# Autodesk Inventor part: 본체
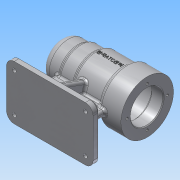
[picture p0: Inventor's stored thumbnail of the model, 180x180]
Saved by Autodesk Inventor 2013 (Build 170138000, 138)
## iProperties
Created: 2016-06
Part Number: 본체
Material: 알루미늄 6061
Document SubType Name: Modeling
Designer: Administrator
Density: 2.71 g/cm^3
Mass: 673.897 g
Surface Area: 647.231 cm^2
Volume: 248.671 cm^3
Author: Administrator
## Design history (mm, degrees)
sketch "스케치1"
  geometry: L1 (-56, 0)-(56, 0); L2 (56, 0)-(56, 34); L3 (56, 34)-(28, 34); L4 (28, 34)-(28, 30); L5 (28, 30)-(-11, 30); L6 (-11, 30)-(-11, 27); L7 (-11, 27)-(-31, 27); L8 (-31, 27)-(-31, 25); L9 (-31, 25)-(-56, 25); L10 (-56, 25)-(-56, 0); 1 further point
  constraints: 20 end point, 6 parallel, 2 vertical, 1 horizontal, 1 midpoint, 1 perpendicular
  dimensions: "d0" = 112 distance of L1.start L1.end; "d2" = 56 distance of point (0, 0) L1.start; "d3" = 68 diameter of L3 L1; "d5" = 60 diameter of L5 L1; "d6" = 54 diameter of L7 L1; "d7" = 50 diameter of L9 L1; "d8" = 25 distance of L8.end L9.end; "d9" = 45 distance between parallel lines of L6 L10; "d10" = 84 distance between parallel lines of L4 L10
revolve "회전1" sketch "스케치1" stored, may be unused: angle "d11" = 90 deg
node "작업 평면1"
sketch "스케치2"
  geometry: L1 (56, 35)-(-56, 35); L2 (-56, 35)-(-56, -35); L3 (-56, -35)-(56, -35); L4 (56, -35)-(56, 35); L5 (56, 35)-(-56, -35); L6 (-56, 35)-(56, -35); 1 further point
  constraints: 12 end point, 2 midpoint, 2 parallel, 1 horizontal, 1 perpendicular
  dimensions: "d13" = 112 distance of L1.start L1.end; "d15" = 70 distance of L1.end L2.end
extrude "돌출1" join sketch "스케치2" distance "d16" = 10; taper "d17" = 0 deg
hole "구멍1" diameter "d20" = 42; stored, may be unused: countersink angle "d24" = 90 deg, drill point angle "d26" = 0 deg; dims "d21" = 6, "d22" = 4, "d23" = 2, "d25" = 15, "d27" = 10, "d28" = 10
hole "구멍2" diameter "d31" = 42; stored, may be unused: countersink angle "d35" = 90 deg, drill point angle "d37" = 0 deg; dims "d29" = 10, "d30" = 10, "d32" = 6, "d33" = 48, "d34" = 54, "d36" = 66
hole "구멍3" diameter "d40" = 32; stored, may be unused: countersink angle "d44" = 90 deg, drill point angle "d46" = 0 deg; dims "d38" = 10, "d39" = 10, "d41" = 6, "d42" = 35, "d43" = 18, "d45" = 22
hole "구멍4" diameter "d49" = 21; stored, may be unused: countersink angle "d53" = 90 deg, drill point angle "d55" = 0 deg; dims "d47" = 10, "d48" = 10, "d50" = 6, "d51" = 35, "d52" = 18, "d54" = 3
sketch "스케치3"
  geometry: L1 (-56, -25)-(-56, 25) reference; L2 (-56, 25)-(-31, 25) reference; L3 (-31, 25)-(-31, 27) reference; L4 (-31, 27)-(-11, 27) reference; L5 (-11, 27)-(-11, 30) reference; L6 (-11, 30)-(28, 30) reference; L7 (28, 30)-(28, 34) reference; L8 (28, 34)-(56, 34) reference; L9 (56, 34)-(56, 21) reference; L10 (56, 21)-(41, 21) reference; L11 (41, 21)-(41, 24) reference; L12 (41, 24)-(-13, 24) reference; L13 (-13, 24)-(-13, 21) reference; L14 (-13, 21)-(-25, 21) reference; L15 (-25, 21)-(-25, 17.5) reference; L16 (-25, 17.5)-(-43, 17.5) reference; L17 (-43, 17.5)-(-43, 16) reference; L18 (-43, 16)-(-47, 16) reference; L19 (-47, 16)-(-47, 10.5) reference; L20 (-47, 10.5)-(-50, 10.5) reference; L21 (-50, 10.5)-(-50, -10.5) reference; L22 (-50, -10.5)-(-47, -10.5) reference; L23 (-47, -10.5)-(-47, -16) reference; L24 (-47, -16)-(-43, -16) reference; L25 (-43, -16)-(-43, -17.5) reference; L26 (-43, -17.5)-(-25, -17.5) reference; L27 (-25, -17.5)-(-25, -21) reference; L28 (-25, -21)-(-13, -21) reference; L29 (-13, -21)-(-13, -24) reference; L30 (-13, -24)-(41, -24) reference; L31 (41, -24)-(41, -21) reference; L32 (41, -21)-(56, -21) reference; L33 (56, -21)-(56, -34) reference; L34 (56, -34)-(28, -34) reference; L35 (28, -34)-(28, -30) reference; L36 (28, -30)-(-11, -30) reference; L37 (-11, -30)-(-11, -27) reference; L38 (-11, -27)-(-31, -27) reference; L39 (-31, -27)-(-31, -25) reference; L40 (-31, -25)-(-56, -25) reference; L41 (56, -60)-(56, -70) reference; L42 (56, -70)-(-56, -70) reference; L43 (-56, -70)-(-56, -60) reference; L44 (-56, -60)-(56, -60) reference; L45 (36, -60)-(36, -34); L46 (-36, -60)-(-36, -25); L47 (36, -60)-(-36, -60); 1 further point
  constraints: 6 end point, 4 point on line, 2 parallel, 1 collinear, 1 perpendicular
  dimensions: "d56" = 20 distance between parallel lines of L46 L43; "d57" = 20 distance between parallel lines of L41 L45
feature "리브1" sketch "스케치3" dims "d58" = 1, "d59" = 8, "d60" = 0, "d61" = 0, "d62" = 1, "d63" = 1
sketch "스케치4"
  geometry: L1 (-70, 35)-(-60, 35) reference; L2 (-60, 35)-(-60, 4) reference; L3 (-60, 4)-(-29.732, 4) reference; L4 (-29.732, -4)-(-60, -4) reference; L5 (-60, -4)-(-60, -35) reference; L6 (-60, -35)-(-70, -35) reference; L7 (-70, -35)-(-70, 35) reference; L8 (-60, 28)-(-25.68, 15.509); C1 r 24 at (0, 0) reference; A1 r 30 centre (0, 0) between (-29.732, -4) and (-29.732, 4) reference; 1 further point
  constraints: 2 end point, 1 point on circle, 1 point on line
  dimensions: "d64" = 110 deg angle of L2 L8; "d67" = 7 distance from line of L1 L8.start
feature "리브2" sketch "스케치4" dims "d68" = 1, "d69" = 8, "d70" = 0, "d71" = 0, "d72" = 1, "d73" = 1
sketch "스케치5"
  geometry: C1 r 21 at (0, 0) reference; 1 further point
  constraints: 1 vertical alignment
  dimensions: "d74" = 26 distance of point (0, 26) C1.centre
hole "구멍5" sketch "스케치5" at (0, 26) diameter "d75" = 3.242; stored, may be unused: countersink angle "d79" = 90 deg, drill point angle "d81" = 118 deg; dims "d76" = 8, "d77" = 35, "d78" = 18, "d80" = 11
sketch "스케치6"
  geometry: 2 further points
  dimensions: "d85" = 46 horizontal distance of point (0, 0) point (-46, 25); "d86" = 25 vertical distance of point (0, 0) point (-46, 25)
hole "구멍6" sketch "스케치6" at (-46, 25) diameter "d87" = 5; stored, may be unused: countersink angle "d91" = 90 deg, drill point angle "d93" = 0 deg; dims "d88" = 8, "d89" = 9, "d90" = 4, "d92" = 10
fillet "모깎기1" dims "d103" = 10
chamfer "모따기2" distance "d104" = 4; stored, may be unused: second distance "d105" = 2, angle "d106" = 45 deg
fillet "모깎기2" dims "d107" = 0.3, "d109" = 10, "d111" = 3
fillet "모깎기3" dims "d110" = 3
chamfer "모따기3" distance "d112" = 1; stored, may be unused: second distance "d113" = 2, angle "d114" = 45 deg
node "작업 평면3"
sketch "스케치8"
  geometry: L1 (47.5, -34)-(47.5, 34) reference; 2 further points
  constraints: 1 horizontal alignment, 1 other
  dimensions: "d119" = 48 distance from line of L1 point (-0.5, 0)
feature "엠보싱2" sketch "스케치8" dims "d0" = 112, "d2" = 56, "d3" = 68, "d5" = 60, "d6" = 54, "d7" = 50, "d8" = 25, "d9" = 45, "d10" = 84, "d120" = 0.5, "d121" = 0
fillet "모깎기6" dims "d123" = 3
fillet "모깎기7" dims "d124" = 3
node "솔리드1"
mirror "대칭1"
pattern_circular "원형 패턴1" dims angle "d83" = 360 deg
pattern_linear "직사각형 패턴1" dims "d96" = 92
node "절단 모서리 투영1"
node "절단 모서리 투영2"
